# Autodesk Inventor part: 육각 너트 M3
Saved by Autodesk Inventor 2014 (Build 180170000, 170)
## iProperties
Created: 2025-09
Part Number: 육각 너트 M3
Material: 일반
Document SubType Name: Modeling
Designer: dg
Density: 1 g/cm^3
Appearance: 기본값
Author: dg
Author: jhkim
Description: 6각 너트 및 6각 가는 너트 - 모따기 안된
Creation Date: 2025-09-02
Sending System: Autodesk Inventor 2026
Preprocessor: ST-DEVELOPER v20.1
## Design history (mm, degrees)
node "육각 너트 M31"
body "Solid1"
node "기준1"
